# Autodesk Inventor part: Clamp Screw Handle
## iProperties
Shininess: 77.0
Length Units: 11269
Angle Units: 11279
Time Units: 11290
Mass Units: 11283
Length Display Precision: 3
Angle Display Precision: 2
Compacted: True
Created: 2002-02
Part Number: Clamp Screw Handle
Document SubType Name: Modeling
Designer: ***
Density: 1 g/cm^3
Density: 0.0
Volumn: 0.0
Area: 0.0
PropertySet Name: Model Information
Control State: 0
Master: False
Checked Out: False
Author: ***
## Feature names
1. Revolution1
